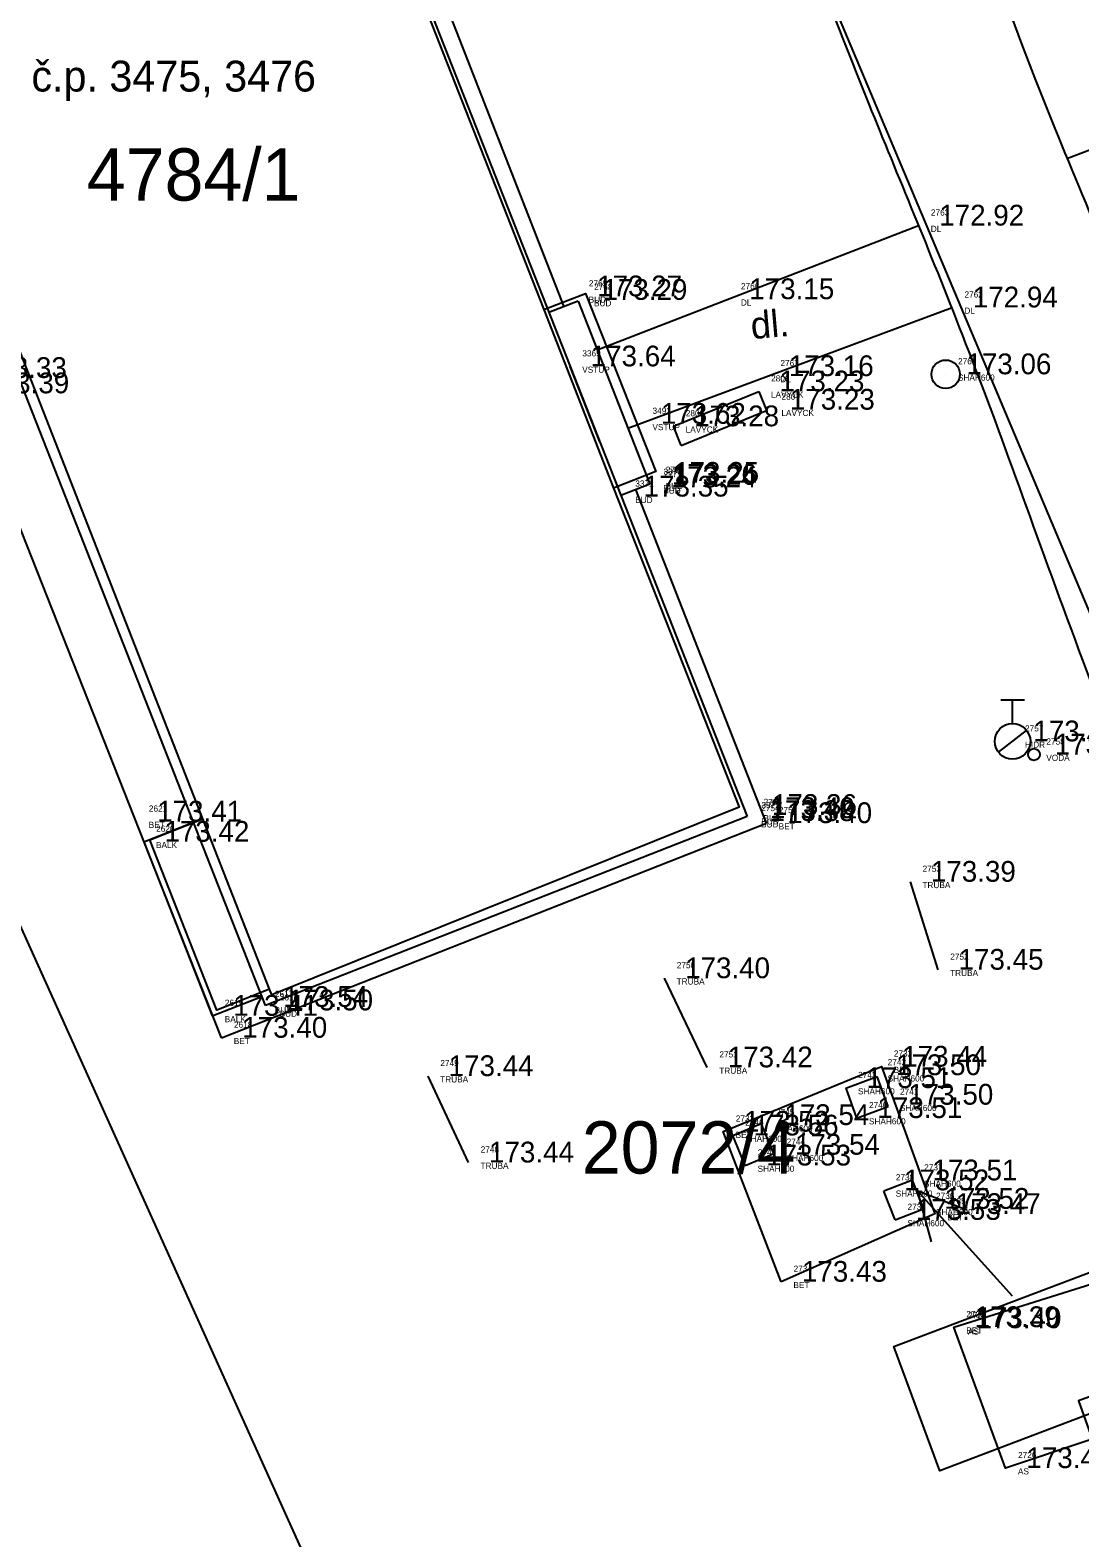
# Model space of a CAD drawing. Extents: x -566117 to -565580, y -1202428 to -1201938.
# Drawn here: x -565732.17 to -565710.06, y -1202063.52 to -1202031.75 of the extents above; entities that cross this region are included whole.
import ezdxf

# ---------------------------------------------------------------- set-up
doc = ezdxf.new("R2010")
doc.units = 0
for name, color, linetype in [('1029', 7, 'Continuous'), ('Bod', 7, 'Continuous'), ('BUDOVY_MĚŘ (Construction)', 7, 'Continuous'), ('CIZÍ_NADZEM', 7, 'Continuous'), ('Implicitní', 7, 'Continuous'), ('Kanalizace', 7, 'Continuous'), ('Katastr', 7, 'Continuous'), ('Kod', 7, 'Continuous'), ('POMOC_POPIS', 7, 'Continuous'), ('Voda', 7, 'Continuous'), ('Výška', 7, 'Continuous'), ('Zpevněné plohy', 7, 'Continuous'), ('Číslo', 7, 'Continuous'), ('Číslo popisné', 7, 'Continuous')]:
    doc.layers.add(name, color=color, linetype=linetype)

# ---------------------------------------------------------------- blocks, each defined once
blk = doc.blocks.new('1029$2')
at = {"layer": 'Katastr'}
for p, q in [((0, 3.001), (-0.501, 2)), ((0, 0), (0, 3.001)), ((0, 3.001), (0.501, 2))]:
    blk.add_line(p, q, dxfattribs=at)
blk = doc.blocks.new('A$C69D74C1E')
at = {"layer": 'Katastr'}
for p, q in [((343.58, 30.8), (345.05, 27.04)), ((337.8, 16.48), (336.4, 20.07))]:
    blk.add_line(p, q, dxfattribs=at)
for points in [[(352.27, -21.85), (342.76, -4.81), (304.34, 80.41), (327.63, 89.54)], [(330.05, 83.8), (363.89, 3.49), (380.17, -34.27), (369.99, -40.48), (374.61, -46.7), (369.18, -49.86), (364.36, -43.48), (363.11, -41.25)], [(334.35, 54.32), (337.02, 47.52), (337.9, 47.87), (339.37, 44.12), (338.49, 43.77), (343.58, 30.8), (344.46, 31.14), (345.94, 27.39), (345.05, 27.04), (347.69, 20.32), (337.85, 16.36), (337.8, 16.48), (336.69, 16.04), (335.28, 19.63), (336.4, 20.07), (332.55, 29.91)], [(357.85, 8.59), (351.92, 6.33), (350.95, 8.95), (356.9, 11.21), (357.85, 8.59)]]:
    blk.add_lwpolyline(points, dxfattribs=at)
at = {"layer": '1029', "rotation": 42}
blk.add_blockref('1029$2', (353.45, 10.01), dxfattribs=at)
at = {"layer": 'Katastr'}
for s, p in [('4784/1', (333.957, 33.097)), ('2072/4', (344.38, 12.597))]:
    blk.add_text(s, height=1.1, dxfattribs=at).set_placement(p)
blk = doc.blocks.new('POINT_DISPLAY')
at = {"layer": 'Implicitní'}
blk.add_line((0, 0), (0, 0), dxfattribs=at)
blk = doc.blocks.new('6.130')
at = {"layer": 'Voda'}
for p, q in [((-0.5, 1.75), (0.5, 1.75)), ((0, 0.75), (0, 1.75)), ((-0.588, -0.462), (0.592, 0.464))]:
    blk.add_line(p, q, dxfattribs=at)
blk.add_circle((0, 0), 0.75, dxfattribs=at)

msp = doc.modelspace()

# ---------------------------------------------------------------- linework, layer by layer
at = {"layer": 'BUDOVY_MĚŘ (Construction)'}
for p, q in [((-565730.515, -1202014.1), (-565717.072, -1202048.322)), ((-565727.213, -1202052.305), (-565740.661, -1202018.049)), ((-565720.625, -1202037.462), (-565721.242, -1202037.704)), ((-565720.625, -1202037.462), (-565719.121, -1202041.319)), ((-565719.121, -1202041.319), (-565719.73, -1202041.558)), ((-565729.777, -1202048.852), (-565728.73, -1202048.44)), ((-565717.071, -1202048.323), (-565727.213, -1202052.305)), ((-565729.777, -1202048.852), (-565728.337, -1202052.522)), ((-565728.337, -1202052.522), (-565727.289, -1202052.111))]:
    msp.add_line(p, q, dxfattribs=at)
at = {"layer": 'Implicitní'}
for p, q in [((-565718.623, -1202040.098), (-565716.826, -1202039.363)), ((-565716.826, -1202039.363), (-565716.66, -1202039.769)), ((-565718.457, -1202040.505), (-565716.66, -1202039.769)), ((-565718.457, -1202040.505), (-565718.623, -1202040.098)), ((-565714.994, -1202054.041), (-565714.328, -1202053.799)), ((-565714.098, -1202054.432), (-565714.328, -1202053.799)), ((-565714.994, -1202054.041), (-565714.764, -1202054.674)), ((-565714.764, -1202054.674), (-565714.098, -1202054.432)), ((-565717.371, -1202055.041), (-565716.771, -1202054.792)), ((-565716.508, -1202055.424), (-565716.771, -1202054.792)), ((-565717.108, -1202055.673), (-565717.371, -1202055.041)), ((-565717.108, -1202055.673), (-565716.508, -1202055.424)), ((-565713.954, -1202056.819), (-565714.189, -1202056.214))]:
    msp.add_line(p, q, dxfattribs=at)
for points in [[(-565713.637, -1202049.695), (-565713.054, -1202051.548)], [(-565718.813, -1202051.727), (-565717.915, -1202053.606)], [(-565723.793, -1202053.79), (-565722.942, -1202055.61)], [(-565716.353, -1202058.123), (-565717.572, -1202054.96), (-565714.243, -1202053.59), (-565713.116, -1202056.695), (-565716.353, -1202058.123)], [(-565713.588, -1202055.981), (-565714.189, -1202056.214)], [(-565713.954, -1202056.819), (-565713.353, -1202056.586), (-565713.588, -1202055.981)]]:
    msp.add_lwpolyline(points, dxfattribs=at)
at = {"layer": 'Kanalizace'}
msp.add_circle((-565712.889, -1202039.002), 0.3, dxfattribs=at)
at = {"layer": 'Voda'}
msp.add_circle((-565711.029, -1202047.014), 0.125, dxfattribs=at)
at = {"layer": 'Zpevněné plohy'}
for p, q in [((-565728.138, -1202052.981), (-565741.865, -1202018.228)), ((-565720.921, -1202037.578), (-565725.968, -1202024.656)), ((-565710.335, -1202034.456), (-565706.988, -1202033.182)), ((-565720.225, -1202038.489), (-565713.462, -1202035.869)), ((-565719.58, -1202040.141), (-565712.754, -1202037.594)), ((-565720.802, -1202038.836), (-565720.176, -1202040.429)), ((-565716.664, -1202048.459), (-565719.412, -1202041.433)), ((-565728.138, -1202052.981), (-565716.664, -1202048.459))]:
    msp.add_line(p, q, dxfattribs=at)
msp.add_lwpolyline([(-565703.923, -1202060.134), (-565704.989, -1202060.467), (-565705.574, -1202059.063), (-565707.392, -1202059.64), (-565710.088, -1202060.631), (-565709.806, -1202061.439), (-565711.627, -1202062.049), (-565712.714, -1202059.079), (-565708.114, -1202057.633), (-565705.282, -1202056.743)], dxfattribs=at)
for points in [[(-565694.915, -1202073.202), (-565696.075, -1202070.267), (-565700.116, -1202060.038), (-565705.065, -1202047.765), (-565708.889, -1202037.779), (-565711.039, -1202032.882), (-565713.382, -1202026.22), (-565716.407, -1202018.729), (-565720.024, -1202009.882), (-565723.123, -1202001.677), (-565726.587, -1201992.843), (-565728.947, -1201987.507), (-565730.196, -1201983.969), (-565730.944, -1201982.037), (-565731.877, -1201979.822), (-565732.166, -1201978.032), (-565731.875, -1201976.463), (-565731.297, -1201975.197), (-565730.44, -1201974.205), (-565729.363, -1201973.701), (-565728.692, -1201973.436), (-565728.343, -1201973.298)], [(-565722.246, -1202013.586), (-565721.563, -1202015.328), (-565720.63, -1202017.707), (-565719.146, -1202021.302), (-565717.65, -1202024.876), (-565715.839, -1202029.996), (-565714.085, -1202034.376), (-565712.057, -1202039.247), (-565709.619, -1202046.324), (-565706.389, -1202053.725), (-565704.358, -1202059.002), (-565703.923, -1202060.134)]]:
    msp.add_open_spline(points, degree=3, dxfattribs=at)

# ---------------------------------------------------------------- block references
at = {"layer": 'Bod'}
for p in [(-565710.272, -1202034.607), (-565713.462, -1202035.869), (-565720.665, -1202037.36), (-565720.555, -1202037.434), (-565717.461, -1202037.42), (-565712.754, -1202037.594), (-565720.802, -1202038.836), (-565716.631, -1202039.041), (-565712.889, -1202039.002), (-565716.826, -1202039.363), (-565716.607, -1202039.748), (-565719.323, -1202040.046), (-565718.623, -1202040.098), (-565719.095, -1202041.384), (-565719.093, -1202041.33), (-565719.045, -1202041.289), (-565719.687, -1202041.579), (-565710.216, -1202044.382), (-565711.48, -1202046.737), (-565711.029, -1202047.014), (-565729.931, -1202048.427), (-565717.034, -1202048.416), (-565717.031, -1202048.354), (-565716.983, -1202048.287), (-565716.664, -1202048.459), (-565729.777, -1202048.852), (-565713.637, -1202049.695), (-565713.054, -1202051.548), (-565718.813, -1202051.727), (-565728.33, -1202052.519), (-565727.276, -1202052.332), (-565727.174, -1202052.405), (-565728.138, -1202052.981), (-565723.793, -1202053.79), (-565717.915, -1202053.606), (-565714.372, -1202053.77), (-565714.243, -1202053.59), (-565714.995, -1202054.041), (-565714.113, -1202054.392), (-565714.764, -1202054.674), (-565717.572, -1202054.96), (-565717.371, -1202055.041), (-565716.724, -1202054.821), (-565722.942, -1202055.61), (-565717.108, -1202055.673), (-565716.499, -1202055.446), (-565713.603, -1202055.987), (-565714.201, -1202056.196), (-565713.353, -1202056.586), (-565713.116, -1202056.695), (-565713.954, -1202056.819), (-565716.353, -1202058.123), (-565712.714, -1202059.079), (-565712.679, -1202059.102), (-565710.088, -1202060.631), (-565711.627, -1202062.049)]:
    msp.add_blockref('POINT_DISPLAY', p, dxfattribs=at)
at = {"layer": 'CIZÍ_NADZEM', "xscale": 0.5, "yscale": 0.5}
msp.add_blockref('6.130', (-565711.48, -1202046.737), dxfattribs=at)
at = {"layer": 'Implicitní'}
msp.add_blockref('A$C69D74C1E', (-566064.93, -1202068.44), dxfattribs=at)

# ---------------------------------------------------------------- texts
at = {"layer": 'Kod'}
for s, p in [('DL', (-565713.202, -1202036.003)), ('BUD', (-565720.406, -1202037.494)), ('BUD', (-565720.295, -1202037.569)), ('DL', (-565717.202, -1202037.555)), ('DL', (-565712.495, -1202037.728)), ('VSTUP', (-565720.542, -1202038.97)), ('DL', (-565716.371, -1202039.175)), ('SHAH600', (-565712.63, -1202039.137)), ('LAVYCK', (-565716.567, -1202039.497)), ('LAVYCK', (-565716.348, -1202039.882)), ('VSTUP', (-565719.064, -1202040.18)), ('LAVYCK', (-565718.364, -1202040.232)), ('BUD', (-565718.836, -1202041.519)), ('BUD', (-565718.833, -1202041.464)), ('BUD', (-565718.785, -1202041.423)), ('BUD', (-565719.427, -1202041.714)), ('HIDR', (-565711.22, -1202046.872)), ('VODA', (-565710.77, -1202047.149)), ('BET', (-565729.671, -1202048.562)), ('BUD', (-565716.775, -1202048.551)), ('BUD', (-565716.771, -1202048.488)), ('BUD', (-565716.724, -1202048.422)), ('BET', (-565716.405, -1202048.593)), ('BALK', (-565729.518, -1202048.986)), ('TRUBA', (-565713.378, -1202049.829)), ('TRUBA', (-565712.795, -1202051.682)), ('TRUBA', (-565718.554, -1202051.861)), ('BALK', (-565728.07, -1202052.654)), ('BUD', (-565727.017, -1202052.466)), ('BUD', (-565726.914, -1202052.54)), ('BET', (-565727.879, -1202053.116)), ('TRUBA', (-565723.533, -1202053.924)), ('TRUBA', (-565717.656, -1202053.741)), ('SHAH600', (-565714.112, -1202053.904)), ('BET', (-565713.983, -1202053.724)), ('SHAH600', (-565714.735, -1202054.175)), ('SHAH600', (-565713.853, -1202054.526)), ('SHAH600', (-565714.505, -1202054.808)), ('BET', (-565717.312, -1202055.094)), ('SHAH600', (-565717.111, -1202055.175)), ('SHAH600', (-565716.464, -1202054.956)), ('TRUBA', (-565722.683, -1202055.744)), ('SHAH600', (-565716.848, -1202055.807)), ('SHAH600', (-565716.24, -1202055.58)), ('SHAH600', (-565713.344, -1202056.121)), ('SHAH600', (-565713.941, -1202056.33)), ('SHAH600', (-565713.094, -1202056.72)), ('BET', (-565712.856, -1202056.83)), ('SHAH600', (-565713.695, -1202056.954)), ('BET', (-565716.094, -1202058.257)), ('BET', (-565712.455, -1202059.214)), ('AS', (-565712.419, -1202059.237)), ('AS', (-565711.367, -1202062.183))]:
    msp.add_text(s, height=0.13, dxfattribs=at).set_placement(p)
at = {"layer": 'POMOC_POPIS'}
msp.add_text('dl.', height=0.57, rotation=4.9059, dxfattribs=at).set_placement((-565716.97, -1202038.263))
at = {"layer": 'Výška'}
for s, p in [('172.92', (-565713.024, -1202035.869)), ('173.27', (-565720.228, -1202037.36)), ('173.29', (-565720.117, -1202037.434)), ('173.15', (-565717.024, -1202037.42)), ('172.94', (-565712.317, -1202037.594)), ('173.64', (-565720.364, -1202038.836)), ('173.06', (-565712.452, -1202039.002)), ('173.33', (-565733.184, -1202039.08)), ('173.16', (-565716.193, -1202039.041)), ('173.39', (-565733.134, -1202039.403)), ('173.23', (-565716.389, -1202039.363)), ('173.23', (-565716.17, -1202039.748)), ('173.62', (-565718.886, -1202040.046)), ('173.28', (-565718.186, -1202040.098)), ('173.35', (-565719.249, -1202041.579)), ('173.24', (-565718.658, -1202041.384)), ('173.26', (-565718.655, -1202041.33)), ('173.25', (-565718.607, -1202041.289)), ('173.20', (-565711.042, -1202046.737)), ('173.22', (-565710.592, -1202047.014)), ('173.41', (-565729.493, -1202048.427)), ('173.38', (-565716.597, -1202048.416)), ('173.40', (-565716.593, -1202048.354)), ('173.36', (-565716.546, -1202048.287)), ('173.40', (-565716.227, -1202048.459)), ('173.42', (-565729.34, -1202048.852)), ('173.39', (-565713.2, -1202049.695)), ('173.40', (-565718.376, -1202051.727)), ('173.45', (-565712.617, -1202051.548)), ('173.54', (-565726.839, -1202052.332)), ('173.41', (-565727.892, -1202052.519)), ('173.50', (-565726.736, -1202052.405)), ('173.40', (-565727.701, -1202052.981)), ('173.42', (-565717.478, -1202053.606)), ('173.44', (-565713.805, -1202053.59)), ('173.44', (-565723.355, -1202053.79)), ('173.50', (-565713.934, -1202053.77)), ('173.51', (-565714.557, -1202054.041)), ('173.50', (-565713.675, -1202054.392)), ('173.54', (-565716.286, -1202054.821)), ('173.51', (-565714.327, -1202054.674)), ('173.52', (-565717.134, -1202054.96)), ('173.56', (-565716.933, -1202055.041)), ('173.54', (-565716.062, -1202055.446)), ('173.44', (-565722.505, -1202055.61)), ('173.53', (-565716.67, -1202055.673)), ('173.51', (-565713.166, -1202055.987)), ('173.52', (-565713.763, -1202056.196)), ('173.53', (-565713.517, -1202056.819)), ('173.52', (-565712.916, -1202056.586)), ('173.47', (-565712.678, -1202056.695)), ('173.43', (-565715.916, -1202058.123)), ('173.39', (-565712.277, -1202059.079)), ('173.40', (-565712.241, -1202059.102)), ('173.45', (-565711.189, -1202062.049))]:
    msp.add_text(s, height=0.4375, dxfattribs=at).set_placement(p)
at = {"layer": 'Číslo'}
for s, p in [('2763', (-565713.199, -1202035.659)), ('2769', (-565720.403, -1202037.15)), ('2768', (-565720.292, -1202037.225)), ('2766', (-565717.199, -1202037.211)), ('2762', (-565712.492, -1202037.385)), ('3369', (-565720.539, -1202038.626)), ('2767', (-565716.368, -1202038.831)), ('2761', (-565712.627, -1202038.793)), ('2806', (-565716.564, -1202039.153)), ('2807', (-565716.345, -1202039.538)), ('3492', (-565719.061, -1202039.836)), ('2808', (-565718.361, -1202039.888)), ('3370', (-565718.83, -1202041.12)), ('2771', (-565718.833, -1202041.175)), ('2770', (-565718.782, -1202041.079)), ('3371', (-565719.424, -1202041.37)), ('2757', (-565711.217, -1202046.528)), ('2758', (-565710.767, -1202046.805)), ('2621', (-565729.668, -1202048.218)), ('2754', (-565716.772, -1202048.207)), ('3372', (-565716.768, -1202048.145)), ('2755', (-565716.721, -1202048.078)), ('2756', (-565716.402, -1202048.249)), ('2620', (-565729.515, -1202048.642)), ('2753', (-565713.375, -1202049.485)), ('2752', (-565712.792, -1202051.338)), ('2750', (-565718.551, -1202051.517)), ('2619', (-565728.067, -1202052.31)), ('2617', (-565727.014, -1202052.123)), ('2616', (-565726.911, -1202052.196)), ('2618', (-565727.876, -1202052.772)), ('2749', (-565723.53, -1202053.58)), ('2751', (-565717.653, -1202053.397)), ('2742', (-565714.109, -1202053.56)), ('2732', (-565713.98, -1202053.38)), ('2743', (-565714.732, -1202053.831)), ('2741', (-565713.85, -1202054.182)), ('2740', (-565714.502, -1202054.464)), ('2733', (-565717.309, -1202054.75)), ('2746', (-565717.108, -1202054.831)), ('2745', (-565716.461, -1202054.612)), ('2744', (-565716.237, -1202055.236)), ('2748', (-565722.68, -1202055.4)), ('2747', (-565716.845, -1202055.463)), ('2737', (-565713.341, -1202055.777)), ('2738', (-565713.938, -1202055.986)), ('2736', (-565713.091, -1202056.376)), ('2735', (-565712.853, -1202056.486)), ('2739', (-565713.692, -1202056.61)), ('2734', (-565716.091, -1202057.913)), ('2728', (-565712.452, -1202058.87)), ('2727', (-565712.416, -1202058.893)), ('2726', (-565711.364, -1202061.839))]:
    msp.add_text(s, height=0.13, dxfattribs=at).set_placement(p)
at = {"layer": 'Číslo popisné'}
msp.add_text('č.p. 3475, 3476', height=0.65, dxfattribs=at).set_placement((-565732.141, -1202033.045))

doc.saveas('drawing.dxf')
